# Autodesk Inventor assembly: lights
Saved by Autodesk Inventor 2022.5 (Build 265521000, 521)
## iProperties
Created: 2024-12
Part Number: lights
Document SubType Name: Assembly
Designer: AdminForWorker
Title: lights
Author: AdminForWorker
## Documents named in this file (3)
- c:\worker\convert-fusion-r05-cosv3\tmp\job-1\35\temp\files\545dca92-a972-481a-9197-dd1a1176500e\lights.iam
- c:\worker\convert-fusion-r05-cosv3\tmp\job-1\35\temp\files\545dca92-a972-481a-9197-dd1a1176500e\led_org.ipt
- c:\worker\convert-fusion-r05-cosv3\tmp\job-1\35\temp\files\545dca92-a972-481a-9197-dd1a1176500e\Part60.ipt
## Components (3 placed, 2 different names)
1. led_org:1
2. led_org:2
3. Part60
